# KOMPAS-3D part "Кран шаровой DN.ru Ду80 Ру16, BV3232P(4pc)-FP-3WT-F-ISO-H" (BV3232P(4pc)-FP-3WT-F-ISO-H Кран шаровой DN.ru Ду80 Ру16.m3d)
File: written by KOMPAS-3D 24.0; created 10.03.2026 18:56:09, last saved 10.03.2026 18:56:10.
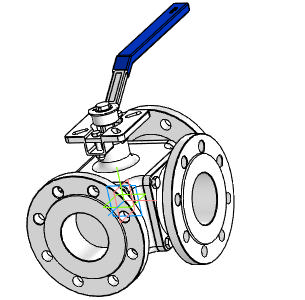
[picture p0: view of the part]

Document properties: Автор: R2D2; Полное имя файла: E:\Работа\Зайцев\BV3232P(4pc)-FP-3WT-F-ISO-H Кран шаровой DN.ru Ду15-100 Ру16\DN80\BV3232P(4pc)-FP-3WT-F-ISO-H Кран шаровой DN.ru Ду80 Ру16.m3d

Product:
- Part/product: Кран шаровой DN.ru Ду80 Ру16  | designation BV3232P(4pc)-FP-3WT-F-ISO-H
    Масса: 39.1
    Раздел спецификации: Прочие изделия
    Примечание: D160-36353

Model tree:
1. Операция без истории:1

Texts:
  BV3232P(4pc)-FP-3WT-F-ISO-H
